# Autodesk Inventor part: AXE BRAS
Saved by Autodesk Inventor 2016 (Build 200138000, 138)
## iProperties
Created: 2013-10
Part Number: AXE BRAS
Material: solidworks materials|Acier allié inoxydable
Document SubType Name: Modeling
Designer: Bruno
Density: 7.3 g/cm^3
Appearance: 198,193,188
Author: Bruno
Sending System: SolidWorks 2013
Last Author: christophe
Last Saved: 2014-02-15
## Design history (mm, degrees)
feature "Chanfrein1"
node "Solide1"
